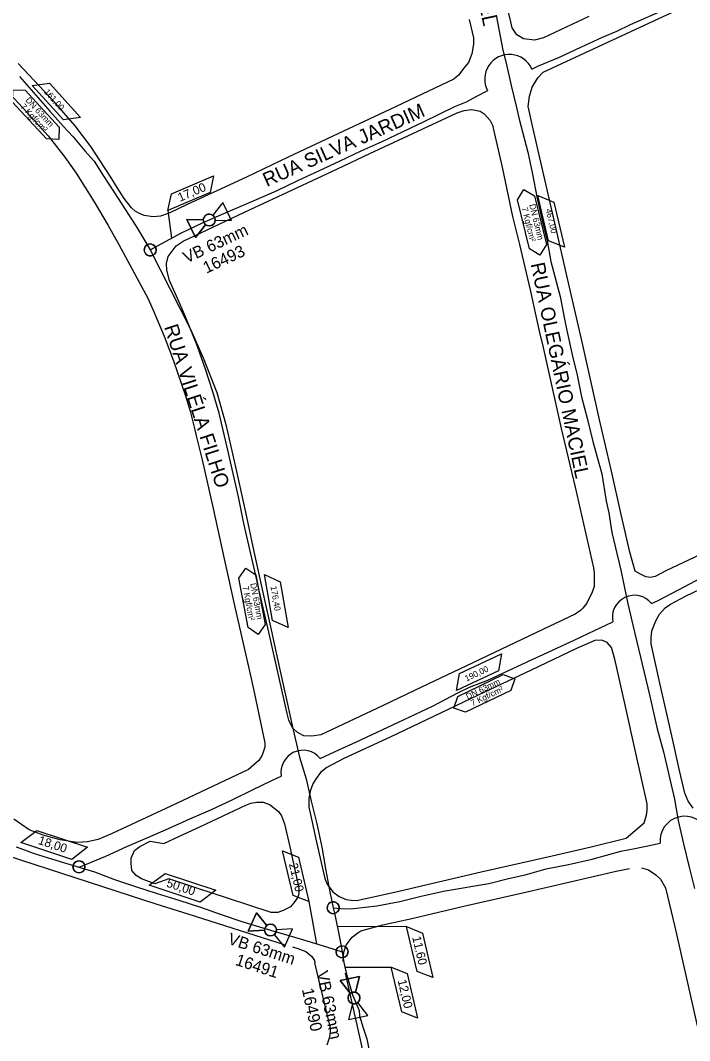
# Model space of a CAD drawing. Extents: x 656692 to 673945, y 7585994 to 7599066.
# Drawn here: x 668655 to 668995, y 7594613 to 7595131 of the extents above; entities that cross this region are included whole.
import ezdxf

# ---------------------------------------------------------------- set-up
doc = ezdxf.new("R2010")
doc.units = 0
for name, color, linetype in [('LOGRADOURO', 7, 'Continuous'), ('LOGRADOURO_TEXTO', 7, 'Continuous'), ('SIMBOLO', 7, 'Continuous'), ('TEXTO', 7, 'Continuous'), ('TUBO_PEAD_GN_63', 7, 'Continuous'), ('VALVULA_PEAD_63', 7, 'Continuous')]:
    doc.layers.add(name, color=color, linetype=linetype)

# ---------------------------------------------------------------- blocks, each defined once
blk = doc.blocks.new('VALVULA_PEAD_DN_16')
at = {"layer": 'VALVULA_PEAD_63'}
for points in [[(-0.0374, 0.0187), (-0.1395, 0.0698), (-0.1395, -0.0698), (-0.0374, -0.0187)], [(-0.0374, -0.0187), (-0.1395, -0.0698), (-0.1395, 0.0698), (-0.0374, 0.0187)], [(0.0374, -0.0187), (0.1395, -0.0698), (0.1395, 0.0698), (0.0374, 0.0187)], [(0.0374, -0.0187), (0.1395, -0.0698), (0.1395, 0.0698), (0.0374, 0.0187)]]:
    blk.add_lwpolyline(points, dxfattribs=at)
blk.add_circle((0, 0), 0.0419, dxfattribs=at)
for start, end in [(90, 270), (153.43495, 206.56505), (270, 90), (333.43495, 26.56505)]:
    blk.add_arc((0, 0), 0.0419, start, end, dxfattribs=at)
blk = doc.blocks.new('INTERLIGACAO_9')
at = {"layer": 'SIMBOLO'}
blk.add_circle((0, 0), 4.19, dxfattribs=at)
for start, end in [(0, 180), (180, 0)]:
    blk.add_arc((0, 0), 4.19, start, end, dxfattribs=at)

msp = doc.modelspace()

# ---------------------------------------------------------------- linework, layer by layer
at = {"layer": 'LOGRADOURO'}
for points in [[(668943.82, 7595133.25), (668920.73, 7595122.42), (668916.09, 7595121.29), (668910.47, 7595121.9), (668907.15, 7595124.02), (668904.8, 7595127.56), (668904.06, 7595130.54), (668898.51, 7595153.33)], [(669022.85, 7594870.61), (668983.2, 7594851.91), (668977.41, 7594848.98), (668975.17, 7594848.42), (668972.68, 7594848.82), (668970, 7594850.15), (668967.37, 7594851.71), (668964.66, 7594861.28), (668960.24, 7594880.42), (668955.24, 7594902.42), (668949.37, 7594927.79), (668940.55, 7594967.22), (668932.36, 7595002.4), (668927.09, 7595025.49), (668924.82, 7595035.74), (668914.99, 7595078.51), (668913.41, 7595085.37), (668912.96, 7595087.64), (668913.64, 7595092.83), (668914.96, 7595097.42), (668917.28, 7595101.38), (668918.01, 7595102.32), (668920.62, 7595105.04), (668925.27, 7595107.28), (668988.53, 7595136.48)], [(668882.94, 7595131.72), (668885.16, 7595122.52), (668885.12, 7595119.31), (668884.31, 7595114.39), (668882.6, 7595110.01), (668880.81, 7595107.84), (668877.51, 7595103.52), (668875.06, 7595101.43), (668842.64, 7595086.04), (668819.05, 7595075.01), (668790.99, 7595061.84), (668769.76, 7595051.77), (668739.64, 7595037.84), (668730.74, 7595033.66), (668727.05, 7595032.23), (668726.1, 7595031.98), (668722.32, 7595031.61), (668717.75, 7595032.3), (668715.66, 7595033.07), (668713.17, 7595034.45), (668711.28, 7595036.08), (668707.61, 7595040.82), (668704.12, 7595046.46), (668700.56, 7595052.29), (668690.57, 7595067.26), (668682.63, 7595077.76), (668672.43, 7595089.62), (668653.7, 7595109.51)], [(668629.94, 7595114.68), (668656.26, 7595086.79), (668668.95, 7595072.77), (668677.49, 7595061.91), (668683.22, 7595053.7), (668692.29, 7595039.17), (668699.5, 7595027.21), (668704.81, 7595017.6), (668719.67, 7594990.22), (668722.32, 7594984.24), (668727.92, 7594970.99), (668732.67, 7594958.38), (668738.76, 7594940.74), (668741.09, 7594932.82), (668743.48, 7594923.37), (668744.27, 7594920.45), (668747.19, 7594908.18), (668752.79, 7594883.42), (668758.44, 7594857.96), (668764.09, 7594832.71), (668772.22, 7594797.13), (668773.75, 7594789.39), (668779.1, 7594764.39), (668779.11, 7594762.28), (668777.7, 7594758.16), (668776.08, 7594755.47), (668770.84, 7594751), (668746.69, 7594739.53), (668733.93, 7594733.46), (668701.41, 7594718.37), (668694.35, 7594715.34), (668688.89, 7594714.13), (668683.46, 7594713.89), (668675.11, 7594715.15), (668666.42, 7594717.55), (668659.36, 7594720.25), (668651.53, 7594725.64)], [(668996.77, 7594731.3), (668994.3, 7594734.86), (668992.52, 7594738.95), (668989.83, 7594750.36), (668985.55, 7594769.59), (668979.88, 7594794.81), (668975.41, 7594814.66), (668975.38, 7594817.86), (668975.8, 7594821.26), (668977.76, 7594826.34), (668979.7, 7594829.78), (668982.57, 7594833.1), (668985.25, 7594834.96), (668992.86, 7594838.88), (669018.19, 7594850.91)], [(668632.94, 7594712.16), (668655.4, 7594704.8), (668723.66, 7594682.78), (668739.95, 7594677.68), (668788.99, 7594662.11)], [(668818.95, 7594653.34), (668819.3, 7594658.18), (668820.5, 7594661.68), (668823.46, 7594665.72), (668826.32, 7594667.97), (668827.87, 7594669.04), (668838.99, 7594672.05), (668853.74, 7594675.25), (668880.86, 7594681.7), (668910.9, 7594688.39), (668957.58, 7594699.35), (668964.35, 7594700.72)], [(668970.58, 7594701.01), (668974.12, 7594699.96), (668977.77, 7594697.47), (668980.15, 7594695.15), (668982.71, 7594690.8), (668987.46, 7594671.01), (668990.26, 7594658.27), (669000.83, 7594611.74)], [(668793.1, 7594660.81), (668795.81, 7594659.95), (668799.95, 7594658.44), (668802.92, 7594655.92), (668804.27, 7594653.96), (668804.45, 7594652.8)], [(668810.7, 7594611.03), (668812.1, 7594615.12), (668812.53, 7594617.91), (668812.24, 7594620.46), (668804.45, 7594652.8)], [(668999.66, 7594556.5), (668983.62, 7594551.67), (668946.17, 7594540.75), (668938.08, 7594538.44), (668906.94, 7594529.43), (668886.53, 7594523.35), (668872.94, 7594519.38), (668864.77, 7594517.21), (668861.11, 7594517.05), (668859.06, 7594517.29), (668856.38, 7594518.31), (668852.55, 7594519.84), (668849.66, 7594522.45), (668848.14, 7594524.77), (668847.28, 7594528.07), (668831.11, 7594598.56), (668820.02, 7594647.41)]]:
    msp.add_lwpolyline(points, dxfattribs=at)
for points in [[(668802.92, 7594767.78), (668798.95, 7594768.07), (668795.75, 7594769.67), (668793.13, 7594772.13), (668791.35, 7594776), (668790.49, 7594779.4), (668781.08, 7594820.68), (668777.1, 7594838.04), (668774.06, 7594851.69), (668768.39, 7594875.78), (668765.7, 7594889.32), (668760.2, 7594913.14), (668755.95, 7594931.86), (668752.73, 7594942.66), (668749.13, 7594953.69), (668744.75, 7594966.27), (668738.78, 7594980.75), (668735.62, 7594988.31), (668730.64, 7594999.27), (668729.25, 7595004.48), (668729.08, 7595007.82), (668730.02, 7595011.51), (668734.06, 7595016.93), (668737.5, 7595019.3), (668771.34, 7595035.22), (668793.08, 7595045.36), (668816.02, 7595056), (668832.39, 7595063.71), (668851.7, 7595072.73), (668876.82, 7595084.41), (668880.33, 7595085.64), (668884.33, 7595086.15), (668888.51, 7595085.22), (668890.57, 7595083.94), (668890.97, 7595083.58), (668893.59, 7595080.52), (668894.82, 7595078.11), (668895.63, 7595074.39), (668899.78, 7595056.83), (668899.94, 7595056.03), (668905, 7595031.81), (668908.59, 7595017.53), (668913.93, 7594994.51), (668918.5, 7594973.6), (668920.55, 7594965.31), (668929.67, 7594924.1), (668936.72, 7594894.3), (668946.09, 7594853.33), (668946.52, 7594850.73), (668946.45, 7594843.8), (668945.51, 7594841.02), (668942.77, 7594835.35), (668940.7, 7594832.77), (668939.58, 7594831.64), (668936.82, 7594829.85), (668913.53, 7594818.76), (668884.78, 7594805.1), (668855.12, 7594791.02), (668838.91, 7594783.32), (668807.53, 7594768.52)], [(668835.8, 7594686.62), (668847.14, 7594689.17), (668889.05, 7594698.93), (668922.91, 7594706.65), (668945.01, 7594711.7), (668962.76, 7594716.1), (668971.82, 7594723.91), (668973.14, 7594727.77), (668973.42, 7594730.23), (668973.42, 7594733.49), (668967.66, 7594759.3), (668962.03, 7594784.41), (668956.9, 7594807.03), (668955.23, 7594812.83), (668953.09, 7594815.4), (668950.32, 7594816.66), (668946.87, 7594816.39), (668937.4, 7594812.35), (668914.4, 7594801.43), (668887.43, 7594788.75), (668842.72, 7594767.32), (668819.29, 7594756.43), (668810.63, 7594752), (668807.37, 7594749.32), (668805.16, 7594746.42), (668803.53, 7594743.64), (668802.11, 7594739.97), (668801.46, 7594736.22), (668801.5, 7594733.08), (668801.45, 7594731.77), (668802.3, 7594728.05), (668805.37, 7594714.1), (668809.65, 7594695.64), (668810.8, 7594692.65), (668813.66, 7594688.87), (668816.87, 7594686.35), (668820.5, 7594684.84), (668823, 7594684.56), (668825.74, 7594684.41)], [(668723.17, 7594692.91), (668716.34, 7594695.41), (668713.67, 7594697.13), (668711.56, 7594699.57), (668711.07, 7594703.12), (668711.22, 7594705.93), (668712.86, 7594709.77), (668715.55, 7594711.9), (668720.87, 7594714.59), (668727.79, 7594713.29), (668735.69, 7594717.06), (668746.39, 7594722.02), (668769.43, 7594732.88), (668771.98, 7594733.83), (668775.1, 7594734.4), (668778.22, 7594734.28), (668781.51, 7594733.18), (668781.99, 7594732.86), (668786.05, 7594729.54), (668787.61, 7594727.42), (668789.11, 7594723.3), (668791.83, 7594711.58), (668796.41, 7594690.69), (668796.38, 7594688.03), (668795.85, 7594686.15), (668793.77, 7594683.14), (668792.15, 7594681.26), (668788.35, 7594679.29), (668785.66, 7594678.38), (668782.31, 7594678.38), (668759.61, 7594685.7), (668745.49, 7594690.28), (668730.34, 7594695.45)]]:
    msp.add_lwpolyline(points, close=True, dxfattribs=at)
at = {"layer": 'SIMBOLO'}
for points in [[(668651.04, 7595096.15), (668657.29, 7595095.9), (668674.6, 7595077.12), (668674.34, 7595070.87), (668668.09, 7595071.13), (668650.78, 7595089.9), (668651.04, 7595096.15)], [(668910.75, 7595045.52), (668916.09, 7595042.28), (668922.15, 7595017.47), (668918.91, 7595012.12), (668913.56, 7595015.37), (668907.5, 7595040.18), (668910.75, 7595045.52)], [(668769.37, 7594853.25), (668774.53, 7594849.72), (668779.26, 7594824.62), (668775.73, 7594819.46), (668770.57, 7594822.98), (668765.84, 7594848.08), (668769.37, 7594853.25)], [(668875.12, 7594782.13), (668877.2, 7594788.03), (668900.21, 7594799.09), (668906.12, 7594797.02), (668904.05, 7594791.12), (668881.03, 7594780.06), (668875.12, 7594782.13)]]:
    msp.add_lwpolyline(points, dxfattribs=at)
at = {"layer": 'TEXTO'}
for p, q in [((668729.83, 7595034.78), (668731.66, 7595020.69)), ((668801.48, 7594683.82), (668805.39, 7594662.35)), ((668851.13, 7594671.12), (668815.92, 7594671.06)), ((668843.36, 7594650.38), (668819.86, 7594650.29))]:
    msp.add_line(p, q, dxfattribs=at)
for points in [[(668669.66, 7595099.43), (668685.42, 7595081.99), (668676.73, 7595080.82), (668660.88, 7595098.36), (668669.66, 7595099.43)], [(668669.66, 7595099.43), (668685.42, 7595081.99), (668676.74, 7595080.81), (668660.88, 7595098.36), (668669.66, 7595099.43)], [(668731.64, 7595043.34), (668752.99, 7595052.49), (668751.31, 7595043.99), (668729.83, 7595034.78), (668731.64, 7595043.34)], [(668731.64, 7595043.33), (668752.99, 7595052.48), (668751.31, 7595043.99), (668729.83, 7595034.78), (668731.64, 7595043.33)], [(668926.01, 7595039.04), (668931.36, 7595016.15), (668923.19, 7595019.32), (668917.81, 7595042.35), (668926.01, 7595039.04)], [(668926.01, 7595039.03), (668931.36, 7595016.15), (668923.19, 7595019.32), (668917.81, 7595042.34), (668926.01, 7595039.03)], [(668786.9, 7594846.16), (668791.02, 7594823.02), (668783.03, 7594826.62), (668778.88, 7594849.9), (668786.9, 7594846.16)], [(668786.9, 7594846.16), (668791.02, 7594823.02), (668783.03, 7594826.62), (668778.88, 7594849.9), (668786.9, 7594846.16)], [(668878.04, 7594799.73), (668899.32, 7594809.7), (668897.91, 7594801.05), (668876.49, 7594791.02), (668878.04, 7594799.73)], [(668878.04, 7594799.73), (668899.33, 7594809.7), (668897.91, 7594801.05), (668876.5, 7594791.02), (668878.04, 7594799.73)], [(668663.23, 7594719.88), (668688.99, 7594711.4), (668680.96, 7594705.26), (668655.04, 7594713.79), (668663.23, 7594719.88)], [(668796.17, 7594706.43), (668801.48, 7594683.82), (668793.4, 7594686.95), (668788.07, 7594709.7), (668796.17, 7594706.43)], [(668728.45, 7594698.19), (668754.21, 7594689.7), (668746.18, 7594683.56), (668720.26, 7594692.1), (668728.45, 7594698.19)], [(668728.45, 7594698.19), (668754.21, 7594689.7), (668746.18, 7594683.56), (668720.26, 7594692.1), (668728.45, 7594698.19)], [(668859.23, 7594667.86), (668864.54, 7594645.24), (668856.46, 7594648.37), (668851.13, 7594671.12), (668859.23, 7594667.86)], [(668851.43, 7594647.29), (668856.73, 7594624.68), (668848.66, 7594627.8), (668843.32, 7594650.56), (668851.43, 7594647.29)], [(668851.43, 7594647.29), (668856.73, 7594624.67), (668848.66, 7594627.8), (668843.32, 7594650.55), (668851.43, 7594647.29)]]:
    msp.add_lwpolyline(points, dxfattribs=at)
at = {"layer": 'TUBO_PEAD_GN_63'}
for points in [[(668914.82, 7595106.62), (668918.25, 7595108.27), (668928.88, 7595112.72), (668939.67, 7595117.8), (668950.77, 7595122.84), (668957.9, 7595125.81), (668964.93, 7595129.21), (668982.74, 7595137.08), (668988.79, 7595140.45), (668998.84, 7595144.42), (669004.12, 7595147.09), (669015.63, 7595152.86), (669025.91, 7595157.37), (669035.74, 7595162.04), (669060.66, 7595173.55), (669064.75, 7595175.74)], [(668896.59, 7595133.94), (668900, 7595116.3), (668901.8, 7595109.58), (668904.32, 7595098.25), (668907.07, 7595087.08), (668908.27, 7595081.24), (668912.71, 7595064.42), (668915.15, 7595053.3), (668917.37, 7595041.8), (668920.09, 7595029.78), (668922.61, 7595019.33), (668924.47, 7595008.86), (668929.11, 7594991.11), (668931.36, 7594979.62), (668932.65, 7594973.91), (668935.47, 7594960.9), (668937.83, 7594951.26), (668940, 7594940.16), (668943.04, 7594928.68), (668945.86, 7594917.49), (668948.75, 7594906.54), (668950.31, 7594901.07), (668952.6, 7594887.18), (668953.94, 7594881.29), (668955.42, 7594871.29), (668960.06, 7594852.08), (668963.5, 7594835.1), (668966.3, 7594823.59), (668969, 7594812.2), (668971.79, 7594800.16), (668974.52, 7594788.91), (668978.52, 7594771.6), (668981.63, 7594759.81), (668984.46, 7594748.25), (668987.23, 7594735.91), (668989.12, 7594725.05), (668991.78, 7594713.21), (668994.73, 7594701.36), (668997.43, 7594690.51)], [(668654.36, 7595102.86), (668669.76, 7595085.23), (668676.61, 7595077.67), (668681.63, 7595072.17), (668687.63, 7595065.15), (668692.35, 7595059.79), (668696.97, 7595052.63), (668702.67, 7595043.78), (668708.24, 7595035.14), (668714.3, 7595025.74), (668720.83, 7595014.79), (668741.07, 7594974.83), (668747.74, 7594959.91), (668754.63, 7594942.32), (668759.25, 7594926.08), (668764.36, 7594903.81), (668769.25, 7594881.55), (668773.47, 7594861.67), (668778.47, 7594839.26), (668782.36, 7594821.84), (668786.58, 7594802.36), (668790.52, 7594784.13), (668792.97, 7594773.32), (668796.62, 7594757.17), (668800.12, 7594746.1), (668802.7, 7594734.77), (668805.5, 7594723.4), (668808.02, 7594711.41), (668810.07, 7594699.68), (668812.05, 7594688.85), (668813.82, 7594680.72), (668814.62, 7594677.36), (668817.21, 7594664.76), (668818.34, 7594658.34), (668819.25, 7594652.95), (668820.46, 7594647.62), (668823.72, 7594636.51), (668827.07, 7594628.55), (668827.14, 7594625.89), (668829.11, 7594619.74), (668830.88, 7594614.19), (668832.53, 7594606.5)], [(668720.83, 7595014.79), (668736.79, 7595023.48), (668747.44, 7595028.49), (668758.23, 7595033.28), (668774.88, 7595040.34), (668785.38, 7595045.04), (668795.88, 7595050.01), (668806.88, 7595055.12), (668817.32, 7595059.98), (668828.07, 7595065.03), (668838.72, 7595069.9), (668849.42, 7595074.95), (668859.64, 7595079.82), (668875.72, 7595087.55), (668881.66, 7595090.07), (668886.79, 7595092.86), (668891.4, 7595095.15), (668892.31, 7595095.63)], [(668975.62, 7594835.23), (668978.96, 7594836.83), (668989.31, 7594842.1), (669000.91, 7594848.18), (669010.84, 7594852.92), (669021.4, 7594858.01), (669034.58, 7594863.81), (669040.56, 7594866.42), (669050.3, 7594870.92), (669061.32, 7594875.99), (669077.24, 7594883.35), (669088.13, 7594888.79), (669099.09, 7594894), (669109.57, 7594898.93), (669120.18, 7594903.68), (669130.89, 7594908.93), (669135.72, 7594911.31)], [(668807.21, 7594756.55), (668814.82, 7594760.07), (668825.66, 7594765.05), (668836.23, 7594769.9), (668846.98, 7594775.04), (668864.24, 7594783.16), (668877.44, 7594789.97), (668883.16, 7594792.69), (668892.4, 7594796.25), (668900.06, 7594799.82), (668909.91, 7594804.45), (668915, 7594806.81), (668920.51, 7594809.37), (668925.68, 7594811.7), (668936.29, 7594816.6), (668947.03, 7594821.75), (668952.45, 7594824.2), (668955.97, 7594825.87)], [(668684.69, 7594701.37), (668698.28, 7594706.96), (668708.91, 7594711.9), (668719.55, 7594716.35), (668730.16, 7594720.97), (668740.95, 7594725.79), (668751.58, 7594730.42), (668762.43, 7594735.58), (668772.86, 7594740.58), (668783.01, 7594745.45), (668787.4, 7594747.53)], [(668813.82, 7594680.72), (668819.49, 7594680.16), (668824.19, 7594680.39), (668836.04, 7594681.69), (668847.67, 7594683.92), (668859.29, 7594686.71), (668870.67, 7594689.32), (668892.89, 7594693.05), (668902.94, 7594695.63), (668911.44, 7594697.46), (668922.07, 7594700.5), (668933.36, 7594702.71), (668945.46, 7594705.34), (668959.93, 7594709.44), (668967.13, 7594710.8), (668976.11, 7594712.59), (668979.97, 7594713.56)], [(668652.78, 7594711.73), (668656.94, 7594710.06), (668661.8, 7594708.3), (668675.01, 7594704.28), (668692.46, 7594699.03), (668702.7, 7594695.13), (668713.4, 7594691.46), (668724.35, 7594687.96), (668735.34, 7594684.5), (668746.31, 7594681.02), (668756.84, 7594677.35), (668767.44, 7594673.72), (668781.99, 7594669.39)], [(668781.99, 7594669.39), (668789.59, 7594667.13), (668800.43, 7594663.87), (668810.34, 7594660.84), (668818.34, 7594658.34)]]:
    msp.add_lwpolyline(points, dxfattribs=at)
for centre, radius, start, end in [((668903.38, 7595101.51), 12.53, 24.0906, 207.9612), ((668966.91, 7594828.2), 11.19, 38.9322, 192.0313), ((668798.49, 7594749.44), 11.25, 39.1845, 189.7422), ((668992.49, 7594714.62), 12.56, 23.7311, 184.8551)]:
    msp.add_arc(centre, radius, start, end, dxfattribs=at)

# ---------------------------------------------------------------- block references
at = {"layer": 'SIMBOLO', "xscale": 0.7229249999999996, "yscale": 0.7229249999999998, "rotation": 166.312122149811}
for p in [(668720.83, 7595014.79), (668684.6, 7594701.48), (668813.82, 7594680.72), (668818.34, 7594658.34)]:
    msp.add_blockref('INTERLIGACAO_9', p, dxfattribs=at)
at = {"layer": 'VALVULA_PEAD_63'}
for p, xscale, yscale, rotation in [((668750.8, 7595029.98), 72.29249999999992, 72.29249999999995, 25.69882932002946), ((668781.96, 7594669.4), 72.29249999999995, 72.29249999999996, -23.80371767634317), ((668824.4, 7594634.9), 72.29249999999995, 72.29249999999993, -78.18143432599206)]:
    msp.add_blockref('VALVULA_PEAD_DN_16', p, dxfattribs=dict(at, xscale=xscale, yscale=yscale, rotation=rotation))

# ---------------------------------------------------------------- texts
for s, rotation, p in [('VB 63mm', 25.048, (668739.31, 7595007.87)), ('16493', 25.048, (668749.4, 7595002.67)), ('VB 63mm', 342.048, (668759.87, 7594662.45)), ('16491', 342.048, (668763.7, 7594651.76)), ('VB 63mm', 282.048, (668805.23, 7594647.96)), ('16490', 282.048, (668797.89, 7594639.3))]:
    msp.add_text(s, height=6, rotation=rotation).set_placement(p)
at = {"layer": 'LOGRADOURO_TEXTO'}
for s, rotation, p in [('RUA OLEGÁRIO MACIEL', 281.8942, (668867.22, 7595237.44)), ('RUA SILVA JARDIM', 24.1047, (668780.06, 7595046.67)), ('RUA OLEGÁRIO MACIEL', 281.8942, (668914.11, 7595007.64)), ('RUA VILÉLA FILHO', 287.9552, (668727.81, 7594975.71))]:
    msp.add_text(s, height=7.2, rotation=rotation, dxfattribs=at).set_placement(p)
at = {"layer": 'TEXTO'}
for s, height, rotation, p in [('161,00', 3.113, 312.1014, (668666.69, 7595094.81)), ('DN 63mm', 3.113, 312.6723, (668657.18, 7595090.63)), ('7 Kgf/cm²', 3.113, 312.6723, (668654.64, 7595087.3)), ('17,00', 4.447, 23.1976, (668735.97, 7595039.18)), ('7 Kgf/cm²', 3.113, 283.7284, (668909.61, 7595036.03)), ('DN 63mm', 3.113, 283.7284, (668913.45, 7595037.72)), ('467,00', 3.113, 283.1575, (668921.79, 7595035.33)), ('7 Kgf/cm²', 3.113, 280.6723, (668767.73, 7594843.83)), ('DN 63mm', 3.113, 280.6723, (668771.65, 7594845.31)), ('176,40', 3.113, 280.1014, (668781.92, 7594843.81)), ('190,00', 3.113, 25.0891, (668881.59, 7594795.54)), ('DN 63mm', 3.113, 25.66, (668882.2, 7594786.39)), ('7 Kgf/cm²', 3.113, 25.66, (668884.64, 7594782.98)), ('18,00', 4.447, 341.7716, (668663.54, 7594713.17)), ('21,00', 4.447, 283.1976, (668791.33, 7594702.89)), ('50,00', 4.447, 341.7716, (668728.76, 7594691.48)), ('11.60', 4.447, 283.1976, (668853.93, 7594665.77)), ('12,00', 4.447, 283.1976, (668846.58, 7594643.75))]:
    msp.add_text(s, height=height, rotation=rotation, dxfattribs=at).set_placement(p)

doc.saveas('drawing.dxf')
